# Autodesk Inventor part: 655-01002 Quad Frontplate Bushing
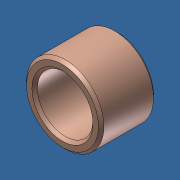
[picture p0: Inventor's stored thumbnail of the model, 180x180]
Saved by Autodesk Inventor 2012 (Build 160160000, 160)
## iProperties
Created: 2013-10
Part Number: 655-01002 Quad Frontplate Bushing
Material: Default
Document SubType Name: Modeling
Designer: Admin
Density: 1 g/cm^3
Author: Admin
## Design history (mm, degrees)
node "655-01002 Quad Frontplate Bushing1"
node "Base1"
body "Solid1"
